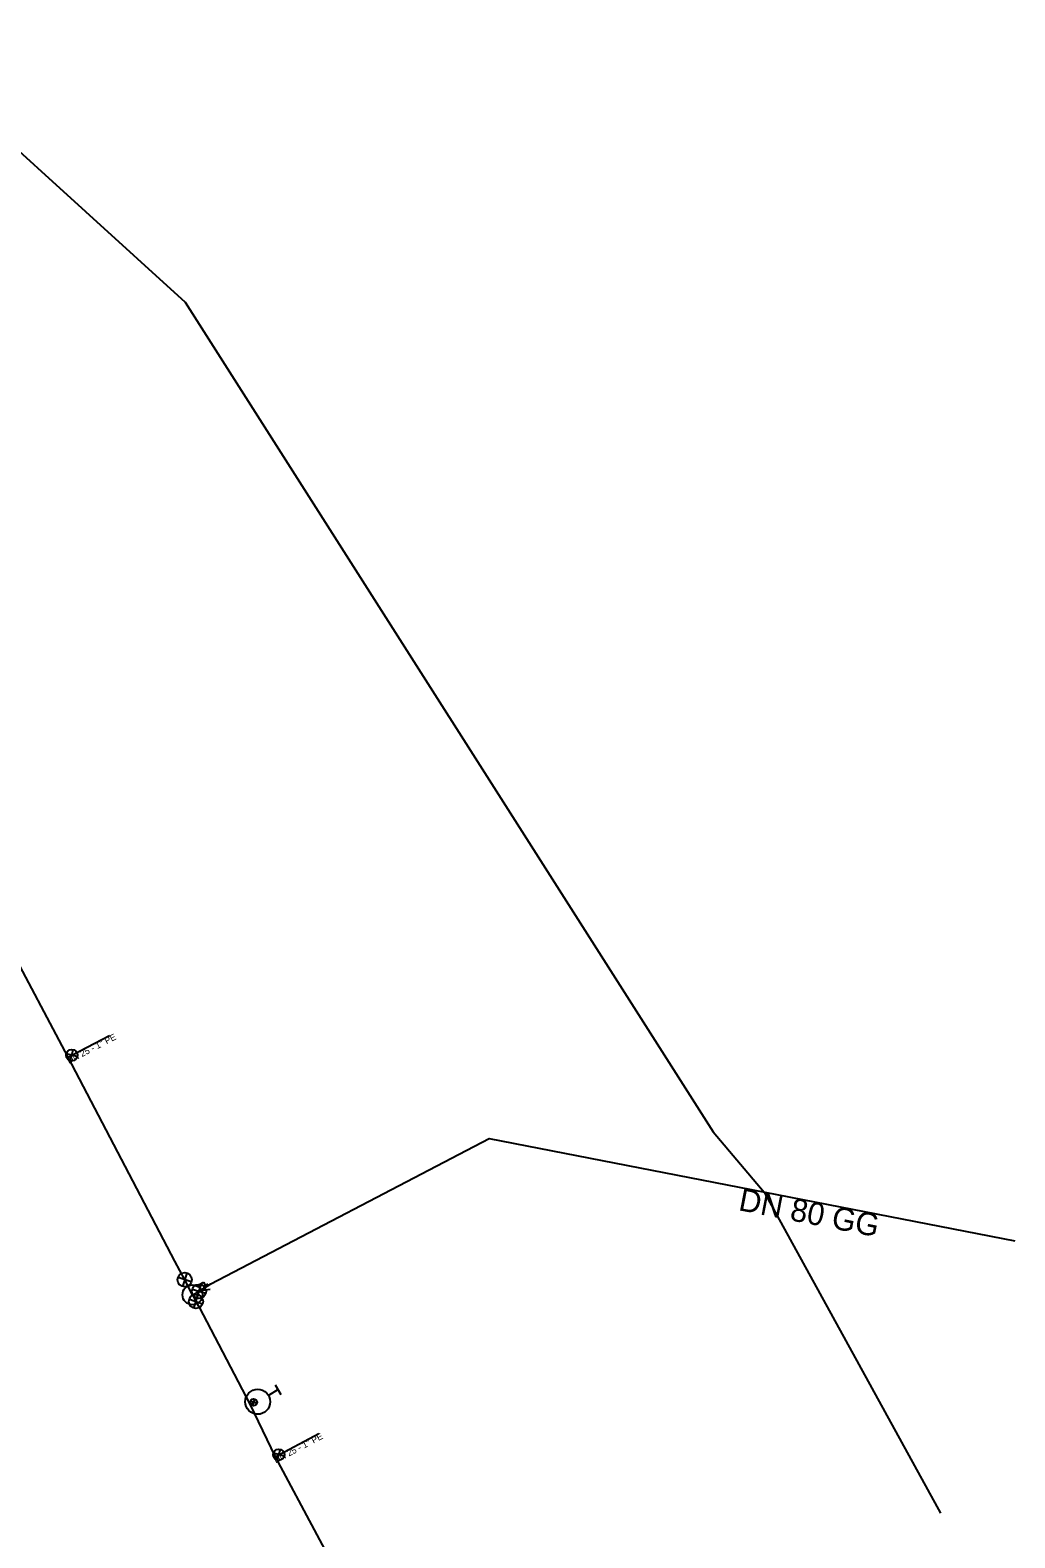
# Model space of a CAD drawing. Extents: x -443519 to -443021, y -1121477 to -1120870.
# Drawn here: x -443449.9 to -443380.3, y -1121058.2 to -1120951.7 of the extents above; entities that cross this region are included whole.
import ezdxf

# ---------------------------------------------------------------- set-up
doc = ezdxf.new("R2010")
doc.units = 0
for name, color, linetype in [('_hydrantova_odbocka_', 7, 'Continuous'), ('_pripojka_priblizne_', 7, 'Continuous'), ('_voda_smvak_prevzato_z_dokumentace_', 7, 'Continuous'), ('Default', 7, 'Continuous'), ('MoLevel 27', 7, 'Continuous'), ('MoLevel 28', 7, 'Continuous'), ('MoLevel 30', 7, 'Continuous'), ('MoLevel 32', 7, 'Continuous'), ('MoLevel 42', 7, 'Continuous'), ('MoLevel 46', 7, 'Continuous'), ('MoLevel 53', 7, 'Continuous')]:
    doc.layers.add(name, color=color, linetype=linetype)

# ---------------------------------------------------------------- blocks, each defined once
blk = doc.blocks.new('_uzaver_')
at = {"layer": 'Default'}
for p, q in [((-0.000035, -0.000035), (0.000035, 0.000035)), ((0.000035, -0.000035), (-0.000035, 0.000035))]:
    blk.add_line(p, q, dxfattribs=at)
for radius in [0.00005, 0.0000025]:
    blk.add_circle((0, 0), radius, dxfattribs=at)
blk = doc.blocks.new('_uzaver_pripojka_')
at = {"layer": 'Default'}
for p, q in [((-0.000035, -0.000035), (0.000035, 0.000035)), ((0.000035, -0.000035), (-0.000035, 0.000035))]:
    blk.add_line(p, q, dxfattribs=at)
for radius in [0.00005, 0.0000025]:
    blk.add_circle((0, 0), radius, dxfattribs=at)
blk = doc.blocks.new('_hydrant_voda_')
at = {"layer": 'Default'}
for p, q in [((-0.0000225, 0.000095), (0.0000225, 0.000095)), ((0, 0.000095), (0, 0.00005))]:
    blk.add_line(p, q, dxfattribs=at)
blk.add_circle((0, 0), 0.00005, dxfattribs=at)
blk = doc.blocks.new('_sachta_voda_')
at = {"layer": 'Default'}
blk.add_lwpolyline([(-0.00001, 0.000065), (0, 0.000035), (0.00001, 0.000065)], dxfattribs=at)
blk.add_circle((0, 0), 0.000035, dxfattribs=at)
blk = doc.blocks.new('_poklop_voda_')
at = {"layer": 'Default'}
blk.add_lwpolyline([(-0.00002, 0.00002), (0.00002, 0.00002), (0.00002, -0.00002), (-0.00002, -0.00002), (-0.00002, 0.00002)], dxfattribs=at)

msp = doc.modelspace()

# ---------------------------------------------------------------- linework, layer by layer
at = {"layer": '_hydrantova_odbocka_'}
msp.add_lwpolyline([(-443434.37, -1121048.78), (-443434.1, -1121048.66), (-443433.81, -1121048.62)], dxfattribs=at)
at = {"layer": '_pripojka_priblizne_'}
for points in [[(-443447.2, -1121024.27), (-443446.94, -1121024.12), (-443444.29, -1121022.74)], [(-443432.58, -1121052.5), (-443432.32, -1121052.36), (-443429.48, -1121050.86)]]:
    msp.add_lwpolyline(points, dxfattribs=at)
at = {"layer": '_voda_smvak_prevzato_z_dokumentace_'}
for p, q in [((-443438.97, -1121039.99), (-443439.66, -1121038.67)), ((-443438.42, -1121041.06), (-443438.97, -1121039.99)), ((-443438.42, -1121041.06), (-443437.96, -1121040.82)), ((-443437.96, -1121040.82), (-443437.11, -1121040.29)), ((-443438.42, -1121041.06), (-443438.17, -1121041.53)), ((-443438.17, -1121041.53), (-443437.95, -1121041.94)), ((-443437.95, -1121041.94), (-443434.37, -1121048.78))]:
    msp.add_line(p, q, dxfattribs=at)
for points in [[(-443460.08, -1120951.67), (-443438.94, -1120970.9), (-443401.64, -1121029.55), (-443398.02, -1121033.8), (-443385.56, -1121056.5)], [(-443439.66, -1121038.67), (-443447.2, -1121024.27), (-443455.75, -1121008.15), (-443467.06, -1120985.91), (-443468.01, -1120983.46), (-443473.93, -1120966.21)], [(-443437.11, -1121040.29), (-443417.46, -1121030.01), (-443380.31, -1121037.24)], [(-443434.37, -1121048.78), (-443432.58, -1121052.5), (-443423.75, -1121069.06), (-443408.88, -1121096.8), (-443400.33, -1121113.1), (-443385.53, -1121141.07), (-443385.18, -1121141.75)]]:
    msp.add_lwpolyline(points, dxfattribs=at)

# ---------------------------------------------------------------- block references
at = {"layer": 'MoLevel 27'}
for p, xscale, yscale, rotation in [((-443438.97, -1121039.99), 10000, 10000, 116.898358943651), ((-443438.17, -1121041.53), 10000, 10000, -63.24478945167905), ((-443437.96, -1121040.82), 10000.000000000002, 9999.999999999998, 27.600080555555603), ((-443434.1, -1121048.66), 5000, 4999.999999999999, 26.3088861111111)]:
    msp.add_blockref('_uzaver_', p, dxfattribs=dict(at, xscale=xscale, yscale=yscale, rotation=rotation))
at = {"layer": 'MoLevel 28', "xscale": 17636.68430335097, "yscale": 17636.684303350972, "rotation": -59.16184444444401}
msp.add_blockref('_hydrant_voda_', (-443433.81, -1121048.62), dxfattribs=at)
at = {"layer": 'MoLevel 30', "xscale": 20000, "yscale": 20000, "rotation": -63.00703025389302}
msp.add_blockref('_sachta_voda_', (-443438.42, -1121041.06), dxfattribs=at)
at = {"layer": 'MoLevel 42', "xscale": 10000, "yscale": 10000, "rotation": -62.20486037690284}
msp.add_blockref('_poklop_voda_', (-443437.73, -1121040.43), dxfattribs=at)
at = {"layer": 'MoLevel 53'}
for p, xscale, yscale, rotation in [((-443446.94, -1121024.12), 7999.999999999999, 7999.999999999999, 30.013252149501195), ((-443432.32, -1121052.36), 8000, 8000, 28.2303381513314)]:
    msp.add_blockref('_uzaver_pripojka_', p, dxfattribs=dict(at, xscale=xscale, yscale=yscale, rotation=rotation))

# ---------------------------------------------------------------- texts
at = {"layer": 'MoLevel 32'}
for rotation, p in [(27.4429, (-443447.15, -1121024.74)), (27.756, (-443432.53, -1121052.98))]:
    msp.add_text("DN 25 - 1'' PE", height=0.455, rotation=rotation, dxfattribs=at).set_placement(p)
at = {"layer": 'MoLevel 46'}
msp.add_text('DN 80 GG', height=1.605, rotation=348.9897, dxfattribs=at).set_placement((-443399.9, -1121035.07))

doc.saveas('drawing.dxf')
